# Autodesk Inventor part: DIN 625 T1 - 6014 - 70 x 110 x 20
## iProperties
Created: 2008-08
Part Number: DIN 625 T1 - 6014 - 70 x 110 x 20
Material: BgAAAEgAAABOAEEATQBFAFMACgBNAGEAdABlAHIAaQBhAGwAcwAKADEAOgBTAHQAZQBlAGwALAAgAE0AaQBsAGQACgAKAEUATgBEAAoAAAA=
Description: Rillenkugellager
Vendor: Autodesk Inc.
Document SubType Name: Modeling
Standard: DIN 625 T1
Designer: U.Rapp
Standards Organization: DIN
Language: de-DE
Size Designation: 6014 - 70 x 110 x 20
Categories: <MemberInstance Version="R10.0.0"><Categories><Category DisplayName="Wellenteile" InternalName="7f7aeb1f-a693-4053-b835-cee3144e0d98" Mnemonic="SHFT"><Category
Author: U.Rapp
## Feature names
1. Körper [Revolution]
2. Rundung1 [Fillet]
3. Kugel [Revolution]
4. Kugeln [Circular Pattern]
